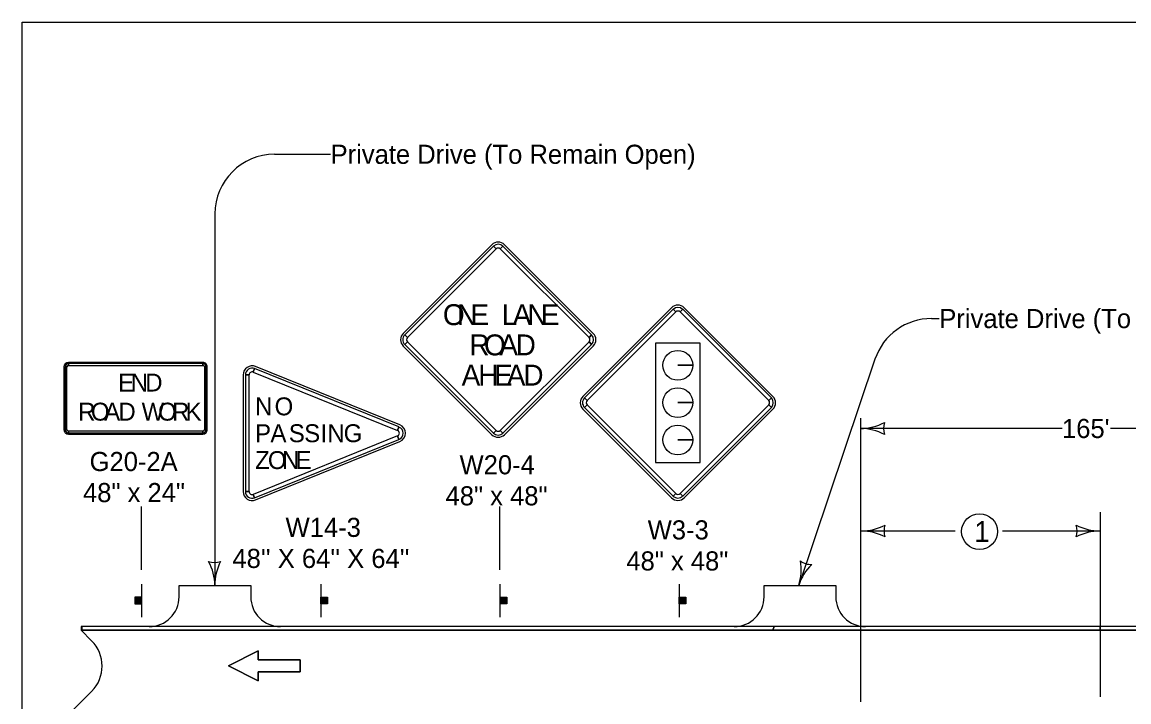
# Model space of a CAD drawing. Extents: x -2134934 to -2127057, y -2139046 to -2137036.
# Drawn here: x -2130232 to -2129305, y -2137605 to -2137036 of the extents above; entities that cross this region are included whole.
import ezdxf

# ---------------------------------------------------------------- set-up
doc = ezdxf.new("R2010")
doc.units = 0
for name, color, linetype in [('Barrier', 7, 'Continuous'), ('BridgeSuperStructureExisting', 7, 'Continuous'), ('Default', 7, 'Continuous'), ('DsnShtPlotIdentification', 7, 'Continuous'), ('DsnShtPlotShape', 7, 'Continuous')]:
    doc.layers.add(name, color=color, linetype=linetype)

msp = doc.modelspace()

# ---------------------------------------------------------------- linework, layer by layer
at = {"layer": 'Barrier'}
for p, q in [((-2129838.72, -2137222.31), (-2129912.96, -2137296.56)), ((-2129837.39, -2137223.64), (-2129835.18, -2137225.85)), ((-2129831.65, -2137225.85), (-2129829.44, -2137223.64)), ((-2129753.86, -2137296.56), (-2129828.11, -2137222.31)), ((-2129688.28, -2137275.12), (-2129762.53, -2137349.37)), ((-2129686.96, -2137276.45), (-2129684.75, -2137278.66)), ((-2129681.21, -2137278.66), (-2129679, -2137276.45)), ((-2129603.43, -2137349.37), (-2129677.68, -2137275.12)), ((-2129909.43, -2137300.09), (-2129911.64, -2137297.88)), ((-2129755.19, -2137297.88), (-2129757.4, -2137300.09)), ((-2129912.96, -2137307.16), (-2129838.72, -2137381.41)), ((-2129911.64, -2137305.84), (-2129909.43, -2137303.63)), ((-2129828.11, -2137381.41), (-2129753.86, -2137307.16)), ((-2129757.4, -2137303.63), (-2129755.19, -2137305.84)), ((-2130196.92, -2137324.64), (-2130196.92, -2137377.14)), ((-2130195.99, -2137324.64), (-2130194.42, -2137324.64)), ((-2130080.67, -2137320.89), (-2130193.17, -2137320.89)), ((-2130193.17, -2137323.39), (-2130193.17, -2137321.82)), ((-2130080.67, -2137321.82), (-2130080.67, -2137323.39)), ((-2130079.42, -2137324.64), (-2130077.86, -2137324.64)), ((-2130076.92, -2137377.14), (-2130076.92, -2137324.64)), ((-2130038.48, -2137329.01), (-2130037.31, -2137326.11)), ((-2129915.78, -2137373.25), (-2130036.61, -2137324.37)), ((-2129670.57, -2137323.34), (-2129683.07, -2137323.34)), ((-2129683.07, -2137323.34), (-2129670.57, -2137323.34)), ((-2130046.92, -2137331.32), (-2130046.92, -2137429.07)), ((-2130045.04, -2137331.32), (-2130041.92, -2137331.32)), ((-2129758.99, -2137352.9), (-2129761.2, -2137350.69)), ((-2129761.2, -2137358.65), (-2129758.99, -2137356.44)), ((-2129670.57, -2137354.59), (-2129683.07, -2137354.59)), ((-2129683.07, -2137354.59), (-2129670.57, -2137354.59)), ((-2129604.76, -2137350.69), (-2129606.96, -2137352.9)), ((-2129606.96, -2137356.44), (-2129604.76, -2137358.65)), ((-2129762.53, -2137359.98), (-2129688.28, -2137434.22)), ((-2129677.68, -2137434.22), (-2129603.43, -2137359.98)), ((-2129916.48, -2137374.98), (-2129917.66, -2137377.88)), ((-2130194.42, -2137377.14), (-2130195.99, -2137377.14)), ((-2130193.17, -2137379.95), (-2130193.17, -2137378.39)), ((-2130193.17, -2137380.89), (-2130080.67, -2137380.89)), ((-2130080.67, -2137378.39), (-2130080.67, -2137379.95)), ((-2130077.86, -2137377.14), (-2130079.42, -2137377.14)), ((-2129917.66, -2137382.52), (-2129916.48, -2137385.41)), ((-2129835.18, -2137377.87), (-2129837.39, -2137380.08)), ((-2129829.44, -2137380.08), (-2129831.65, -2137377.87)), ((-2130036.61, -2137436.03), (-2129915.78, -2137387.15)), ((-2129670.57, -2137385.84), (-2129683.07, -2137385.84)), ((-2129683.07, -2137385.84), (-2129670.57, -2137385.84)), ((-2130041.92, -2137429.07), (-2130045.04, -2137429.07)), ((-2129684.75, -2137430.69), (-2129686.96, -2137432.9)), ((-2129679, -2137432.9), (-2129681.21, -2137430.69)), ((-2130037.31, -2137434.29), (-2130038.48, -2137431.39))]:
    msp.add_line(p, q, dxfattribs=at)
for points in [[(-2129837.39, -2137223.64), (-2129911.64, -2137297.88), (-2129909.43, -2137300.09), (-2129835.18, -2137225.85), (-2129837.39, -2137223.64)], [(-2129755.19, -2137297.88), (-2129829.44, -2137223.64), (-2129831.65, -2137225.85), (-2129757.4, -2137300.09), (-2129755.19, -2137297.88)], [(-2129686.96, -2137276.45), (-2129761.2, -2137350.69), (-2129758.99, -2137352.9), (-2129684.75, -2137278.66), (-2129686.96, -2137276.45)], [(-2129604.76, -2137350.69), (-2129679, -2137276.45), (-2129681.21, -2137278.66), (-2129606.96, -2137352.9), (-2129604.76, -2137350.69)], [(-2129911.64, -2137305.84), (-2129837.39, -2137380.08), (-2129835.18, -2137377.87), (-2129909.43, -2137303.63), (-2129911.64, -2137305.84)], [(-2129829.44, -2137380.08), (-2129755.19, -2137305.84), (-2129757.4, -2137303.63), (-2129831.65, -2137377.87), (-2129829.44, -2137380.08)], [(-2129664.25, -2137304.73), (-2129701.71, -2137304.73), (-2129701.71, -2137404.62), (-2129664.25, -2137404.62), (-2129664.25, -2137304.73)], [(-2130195.99, -2137324.64), (-2130195.99, -2137377.14), (-2130194.42, -2137377.14), (-2130194.42, -2137324.64), (-2130195.99, -2137324.64)], [(-2130080.67, -2137321.82), (-2130193.17, -2137321.82), (-2130193.17, -2137323.39), (-2130080.67, -2137323.39), (-2130080.67, -2137321.82)], [(-2130077.86, -2137377.14), (-2130077.86, -2137324.64), (-2130079.42, -2137324.64), (-2130079.42, -2137377.14), (-2130077.86, -2137377.14)], [(-2129916.48, -2137374.98), (-2130037.31, -2137326.11), (-2130038.48, -2137329.01), (-2129917.66, -2137377.88), (-2129916.48, -2137374.98)], [(-2130045.04, -2137331.32), (-2130045.04, -2137429.07), (-2130041.92, -2137429.07), (-2130041.92, -2137331.32), (-2130045.04, -2137331.32)], [(-2129761.2, -2137358.65), (-2129686.96, -2137432.9), (-2129684.75, -2137430.69), (-2129758.99, -2137356.44), (-2129761.2, -2137358.65)], [(-2129679, -2137432.9), (-2129604.76, -2137358.65), (-2129606.96, -2137356.44), (-2129681.21, -2137430.69), (-2129679, -2137432.9)], [(-2130193.17, -2137379.95), (-2130080.67, -2137379.95), (-2130080.67, -2137378.39), (-2130193.17, -2137378.39), (-2130193.17, -2137379.95)], [(-2130037.31, -2137434.29), (-2129916.48, -2137385.41), (-2129917.66, -2137382.52), (-2130038.48, -2137431.39), (-2130037.31, -2137434.29)]]:
    msp.add_lwpolyline(points, close=True, dxfattribs=at)
for centre in [(-2129683.07, -2137323.34), (-2129683.07, -2137354.59), (-2129683.07, -2137385.84)]:
    msp.add_circle(centre, 12.5, dxfattribs=at)
for centre, radius, start, end in [((-2129833.41, -2137227.61), 7.5, 44.99999, 134.99974), ((-2129833.41, -2137227.61), 5.62, 44.99999, 134.99974), ((-2129833.41, -2137227.61), 2.5, 44.99999, 134.99974), ((-2129682.98, -2137280.43), 7.5, 44.99999, 134.99974), ((-2129682.98, -2137280.43), 5.62, 44.99999, 134.99974), ((-2129682.98, -2137280.43), 2.5, 44.99999, 134.99974), ((-2129907.66, -2137301.86), 7.5, 134.99974, 224.99995), ((-2129907.66, -2137301.86), 5.62, 134.99974, 224.99995), ((-2129907.66, -2137301.86), 2.5, 134.99974, 224.99995), ((-2129759.17, -2137301.86), 2.5, 315.00016, 44.9998), ((-2129759.17, -2137301.86), 5.62, 315.00016, 44.9998), ((-2129759.17, -2137301.86), 7.5, 315.00016, 44.9998), ((-2130193.17, -2137324.64), 3.75, 90.00021, 179.99985), ((-2130193.17, -2137324.64), 2.81, 90.00021, 179.99985), ((-2130193.17, -2137324.64), 1.25, 90.00021, 179.99985), ((-2130080.67, -2137324.64), 3.75, 0, 90.00021), ((-2130080.67, -2137324.64), 2.81, 0, 90.00021), ((-2130080.67, -2137324.64), 1.25, 0, 90.00021), ((-2130039.42, -2137331.32), 7.5, 67.97571, 179.99985), ((-2130039.42, -2137331.32), 5.62, 67.97571, 179.99985), ((-2130039.42, -2137331.32), 2.5, 67.97571, 179.99985), ((-2129757.23, -2137354.67), 7.5, 134.99974, 224.99995), ((-2129757.23, -2137354.67), 5.62, 134.99974, 224.99995), ((-2129757.23, -2137354.67), 2.5, 134.99974, 224.99995), ((-2129608.73, -2137354.67), 2.5, 315.00016, 44.9998), ((-2129608.73, -2137354.67), 5.62, 315.00016, 44.9998), ((-2129608.73, -2137354.67), 7.5, 315.00016, 44.9998), ((-2129918.59, -2137380.2), 5.62, 292.02456, 67.97541), ((-2129918.59, -2137380.2), 7.5, 292.02456, 67.97598), ((-2130193.17, -2137377.14), 3.75, 179.99985, 270.00006), ((-2130193.17, -2137377.14), 2.81, 179.99985, 270.00006), ((-2130193.17, -2137377.14), 1.25, 179.99985, 270.00006), ((-2130080.67, -2137377.14), 3.75, 270.00006, 0.00027), ((-2130080.67, -2137377.14), 2.81, 270.00006, 0.00027), ((-2130080.67, -2137377.14), 1.25, 270.00006, 0.00027), ((-2129918.59, -2137380.2), 2.5, 292.02456, 67.97541), ((-2129833.41, -2137376.11), 7.5, 224.99995, 315.00016), ((-2129833.41, -2137376.11), 5.62, 224.99995, 315.00016), ((-2129833.41, -2137376.11), 2.5, 224.99995, 315.00016), ((-2130039.42, -2137429.07), 7.5, 179.99985, 292.02456), ((-2130039.42, -2137429.07), 5.62, 179.99985, 292.02456), ((-2130039.42, -2137429.07), 2.5, 179.99985, 292.02456), ((-2129682.98, -2137428.92), 2.5, 224.99995, 315.00016), ((-2129682.98, -2137428.92), 7.5, 224.99995, 315.00016), ((-2129682.98, -2137428.92), 5.62, 224.99995, 315.00016)]:
    msp.add_arc(centre, radius, start, end, dxfattribs=at)
at = {"layer": 'BridgeSuperStructureExisting'}
for p, q in [((-2130020.59, -2137146.61), (-2129973.72, -2137146.61)), ((-2130070.59, -2137196.61), (-2130070.59, -2137507.67)), ((-2129470.64, -2137284.15), (-2129464.16, -2137284.15)), ((-2129518.02, -2137318.18), (-2129581.87, -2137507.67)), ((-2129530.12, -2137367.55), (-2129530.12, -2137605.16)), ((-2129361.44, -2137376.23), (-2129530.12, -2137376.23)), ((-2129152.26, -2137376.23), (-2129320.94, -2137376.23)), ((-2130131.95, -2137494.5), (-2130131.95, -2137441.62)), ((-2129831.95, -2137494.5), (-2129831.95, -2137441.62)), ((-2129329.62, -2137446.18), (-2129329.62, -2137601.07)), ((-2129450.84, -2137462.08), (-2129529.62, -2137462.08)), ((-2129329.62, -2137462.08), (-2129411.39, -2137462.08)), ((-2130131.95, -2137506.66), (-2130131.95, -2137534.16)), ((-2129981.95, -2137506.66), (-2129981.95, -2137534.16)), ((-2129831.95, -2137506.66), (-2129831.95, -2137534.16)), ((-2129681.95, -2137506.66), (-2129681.95, -2137534.16)), ((-2130137.28, -2137517.52), (-2130137.28, -2137523.11)), ((-2130136.96, -2137523.11), (-2130136.96, -2137517.52)), ((-2130136.73, -2137517.52), (-2130136.73, -2137523.11)), ((-2130136.41, -2137523.11), (-2130136.41, -2137517.52)), ((-2130136.19, -2137517.52), (-2130136.21, -2137523.11)), ((-2130135.78, -2137523.11), (-2130135.76, -2137517.52)), ((-2130135.55, -2137517.52), (-2130135.55, -2137523.11)), ((-2130135.12, -2137523.11), (-2130135.12, -2137517.52)), ((-2130134.75, -2137517.52), (-2130134.75, -2137523.11)), ((-2130134.43, -2137523.11), (-2130134.41, -2137517.52)), ((-2130134.2, -2137517.52), (-2130134.2, -2137523.11)), ((-2130133.94, -2137523.11), (-2130133.94, -2137517.52)), ((-2130133.6, -2137517.52), (-2130133.6, -2137523.11)), ((-2130133.4, -2137523.11), (-2130133.4, -2137517.52)), ((-2130133.17, -2137517.52), (-2130133.17, -2137523.11)), ((-2130132.91, -2137523.11), (-2130132.91, -2137517.52)), ((-2130132.65, -2137517.52), (-2130132.65, -2137523.11)), ((-2130132.36, -2137523.11), (-2130132.36, -2137517.52)), ((-2129981.54, -2137523.11), (-2129981.54, -2137517.52)), ((-2129981.26, -2137517.52), (-2129981.26, -2137523.11)), ((-2129980.99, -2137523.11), (-2129980.99, -2137517.52)), ((-2129980.73, -2137517.52), (-2129980.73, -2137523.11)), ((-2129980.51, -2137523.11), (-2129980.51, -2137517.52)), ((-2129980.3, -2137517.52), (-2129980.3, -2137523.11)), ((-2129979.96, -2137523.11), (-2129979.96, -2137517.52)), ((-2129979.7, -2137517.52), (-2129979.7, -2137523.11)), ((-2129979.47, -2137523.11), (-2129979.49, -2137517.52)), ((-2129979.16, -2137517.52), (-2129979.16, -2137523.11)), ((-2129978.78, -2137523.11), (-2129978.78, -2137517.52)), ((-2129978.35, -2137517.52), (-2129978.35, -2137523.11)), ((-2129978.12, -2137523.11), (-2129978.14, -2137517.52)), ((-2129977.71, -2137517.52), (-2129977.69, -2137523.11)), ((-2129977.49, -2137523.11), (-2129977.49, -2137517.52)), ((-2129977.17, -2137517.52), (-2129977.17, -2137523.11)), ((-2129976.94, -2137523.11), (-2129976.94, -2137517.52)), ((-2129976.62, -2137517.52), (-2129976.62, -2137523.11)), ((-2129831.54, -2137523.11), (-2129831.54, -2137517.52)), ((-2129831.26, -2137517.52), (-2129831.26, -2137523.11)), ((-2129830.99, -2137523.11), (-2129830.99, -2137517.52)), ((-2129830.73, -2137517.52), (-2129830.73, -2137523.11)), ((-2129830.51, -2137523.11), (-2129830.51, -2137517.52)), ((-2129830.3, -2137517.52), (-2129830.3, -2137523.11)), ((-2129829.96, -2137523.11), (-2129829.96, -2137517.52)), ((-2129829.7, -2137517.52), (-2129829.7, -2137523.11)), ((-2129829.47, -2137523.11), (-2129829.49, -2137517.52)), ((-2129829.16, -2137517.52), (-2129829.16, -2137523.11)), ((-2129828.78, -2137523.11), (-2129828.78, -2137517.52)), ((-2129828.35, -2137517.52), (-2129828.35, -2137523.11)), ((-2129828.12, -2137523.11), (-2129828.14, -2137517.52)), ((-2129827.71, -2137517.52), (-2129827.69, -2137523.11)), ((-2129827.49, -2137523.11), (-2129827.49, -2137517.52)), ((-2129827.17, -2137517.52), (-2129827.17, -2137523.11)), ((-2129826.94, -2137523.11), (-2129826.94, -2137517.52)), ((-2129826.62, -2137517.52), (-2129826.62, -2137523.11)), ((-2129681.54, -2137523.11), (-2129681.54, -2137517.52)), ((-2129681.26, -2137517.52), (-2129681.26, -2137523.11)), ((-2129680.99, -2137523.11), (-2129680.99, -2137517.52)), ((-2129680.73, -2137517.52), (-2129680.73, -2137523.11)), ((-2129680.51, -2137523.11), (-2129680.51, -2137517.52)), ((-2129680.3, -2137517.52), (-2129680.3, -2137523.11)), ((-2129679.96, -2137523.11), (-2129679.96, -2137517.52)), ((-2129679.7, -2137517.52), (-2129679.7, -2137523.11)), ((-2129679.48, -2137523.11), (-2129679.49, -2137517.52)), ((-2129679.16, -2137517.52), (-2129679.16, -2137523.11)), ((-2129678.78, -2137523.11), (-2129678.78, -2137517.52)), ((-2129678.35, -2137517.52), (-2129678.35, -2137523.11)), ((-2129678.13, -2137523.11), (-2129678.14, -2137517.52)), ((-2129677.71, -2137517.52), (-2129677.69, -2137523.11)), ((-2129677.49, -2137523.11), (-2129677.49, -2137517.52)), ((-2129677.17, -2137517.52), (-2129677.17, -2137523.11)), ((-2129676.94, -2137523.11), (-2129676.94, -2137517.52)), ((-2129676.63, -2137517.52), (-2129676.63, -2137523.11)), ((-2130182.57, -2137545.16), (-2130173.79, -2137553.95)), ((-2128680.12, -2137545.16), (-2130182.57, -2137545.16)), ((-2130182.57, -2137545.16), (-2130173.78, -2137553.95)), ((-2130015.59, -2137542.16), (-2130125.59, -2137542.16)), ((-2129525.87, -2137542.16), (-2129635.87, -2137542.16)), ((-2130173.78, -2137596.37), (-2130191.36, -2137613.95)), ((-2130173.79, -2137596.38), (-2130191.36, -2137613.95))]:
    msp.add_line(p, q, dxfattribs=at)
for points in [[(-2130100.59, -2137517.16), (-2130100.59, -2137507.67), (-2130040.59, -2137507.67), (-2130040.59, -2137517.16)], [(-2129610.87, -2137517.16), (-2129610.87, -2137507.67), (-2129550.87, -2137507.67), (-2129550.87, -2137517.16)], [(-2130034.3, -2137579.99), (-2130034.3, -2137587.49), (-2130059.3, -2137574.99), (-2130034.3, -2137562.49), (-2130034.3, -2137569.99), (-2129999.3, -2137569.99), (-2129999.3, -2137579.99), (-2130034.3, -2137579.99)]]:
    msp.add_lwpolyline(points, dxfattribs=at)
for points in [[(-2130132.05, -2137523.11), (-2130132.05, -2137517.48), (-2130137.67, -2137517.48), (-2130137.67, -2137523.11)], [(-2129981.86, -2137523.11), (-2129981.86, -2137517.48), (-2129976.23, -2137517.48), (-2129976.23, -2137523.11)], [(-2129831.86, -2137523.11), (-2129831.86, -2137517.48), (-2129826.23, -2137517.48), (-2129826.23, -2137523.11)], [(-2129681.86, -2137523.11), (-2129681.86, -2137517.48), (-2129676.23, -2137517.48), (-2129676.23, -2137523.11)], [(-2129999.3, -2137579.99), (-2129999.3, -2137569.99), (-2130034.3, -2137569.99), (-2130034.3, -2137562.49), (-2130059.3, -2137574.99), (-2130034.3, -2137587.49), (-2130034.3, -2137579.99)]]:
    msp.add_lwpolyline(points, close=True, dxfattribs=at)
msp.add_circle((-2129430.48, -2137462.58), 15, dxfattribs=at)
for centre, radius, start, end in [((-2130020.59, -2137196.61), 50, 90, 180), ((-2129470.64, -2137334.15), 50, 90, 161.37877), ((-2129529.62, -2137419.58), 42.5, 270, 298.07249), ((-2129493.99, -2137462.08), 16.42, 162.26665, 197.73335), ((-2129365.26, -2137462.08), 16.42, 342.26665, 17.73335), ((-2129329.62, -2137419.58), 42.5, 241.92751, 270), ((-2129529.62, -2137504.58), 42.5, 61.92751, 90), ((-2129329.62, -2137504.58), 42.5, 90, 118.07249), ((-2130125.59, -2137517.16), 25, 270, 360), ((-2130015.59, -2137517.16), 25, 180, 270), ((-2129635.87, -2137517.16), 25, 270, 360), ((-2129525.87, -2137517.16), 25, 180, 270), ((-2130195, -2137575.16), 30, 315, 45), ((-2130195, -2137575.16), 30, 315, 45)]:
    msp.add_arc(centre, radius, start, end, dxfattribs=at)
at = {"layer": 'Default'}
msp.add_lwpolyline([(-2130231.95, -2137035.95), (-2127096.96, -2137035.95), (-2127096.96, -2139045.94), (-2130231.95, -2139045.94)], close=True, dxfattribs=at)
at = {"layer": 'DsnShtPlotIdentification'}
for p, q in [((-2128680.12, -2137542.16), (-2130182.57, -2137542.16)), ((-2130182.57, -2137542.16), (-2130182.57, -2137545.16)), ((-2129602.5, -2137542.16), (-2130182.57, -2137542.16)), ((-2128680.12, -2137545.16), (-2130182.57, -2137545.16)), ((-2130182.57, -2137545.16), (-2129603.51, -2137545.16)), ((-2130181.95, -2137542.16), (-2130181.95, -2137545.16)), ((-2129602.5, -2137542.16), (-2129603.51, -2137545.16)), ((-2129603.51, -2137545.16), (-2129602.5, -2137542.16)), ((-2129603.51, -2137545.16), (-2129329.62, -2137545.16)), ((-2129329.62, -2137542.16), (-2129602.5, -2137542.16)), ((-2129329.62, -2137542.16), (-2129329.62, -2137545.16)), ((-2129296.37, -2137542.16), (-2129329.62, -2137542.16)), ((-2129329.62, -2137545.16), (-2129329.62, -2137542.16)), ((-2129329.62, -2137545.16), (-2129296.24, -2137545.16))]:
    msp.add_line(p, q, dxfattribs=at)
msp.add_lwpolyline([(-2130182.37, -2137545.16), (-2128872.37, -2137545.16)], dxfattribs=at)
at = {"layer": 'DsnShtPlotShape'}
for centre, radius, start, end in [((-2129530.12, -2137333.73), 42.5, 270, 298.07249), ((-2129494.48, -2137376.23), 16.42, 162.26665, 197.73335), ((-2129530.12, -2137418.73), 42.5, 61.92751, 90), ((-2130071.03, -2137472.04), 16.42, 252.97281, 288.43951), ((-2130113.08, -2137508.19), 42.5, 0.70616, 28.77865), ((-2130028.09, -2137507.15), 42.5, 152.63367, 180.70616), ((-2129622.31, -2137494.6), 42.5, 342.08492, 10.15741), ((-2129541.43, -2137520.74), 42.5, 134.01243, 162.08492), ((-2129570.91, -2137473.76), 16.42, 234.35157, 269.81827)]:
    msp.add_arc(centre, radius, start, end, dxfattribs=at)

# ---------------------------------------------------------------- texts
at = {"layer": 'Barrier'}
for s, height, p in [('O', 17.5, (-2129879.7, -2137289.67)), ('N', 17.5, (-2129867.92, -2137289.67)), ('E', 17.5, (-2129856.7, -2137289.67)), ('L', 17.5, (-2129830.45, -2137289.67)), ('A', 17.5, (-2129821.25, -2137289.67)), ('N', 17.5, (-2129808.98, -2137289.67)), ('E', 17.5, (-2129797.75, -2137289.67)), ('R', 17.5, (-2129857.59, -2137314.98)), ('O', 17.5, (-2129845.3, -2137314.98)), ('A', 17.5, (-2129832.46, -2137314.98)), ('D', 17.5, (-2129818.81, -2137314.98)), ('A', 17.5, (-2129864.03, -2137340.3)), ('H', 17.5, (-2129850.16, -2137340.3)), ('E', 17.5, (-2129836.95, -2137340.3)), ('A', 17.5, (-2129826.23, -2137340.3)), ('D', 17.5, (-2129812.37, -2137340.3)), ('E', 15, (-2130151.6, -2137345.26)), ('N', 15, (-2130140.98, -2137345.26)), ('D', 15, (-2130128.89, -2137345.26)), ('R', 15, (-2130185.06, -2137369.64)), ('O', 15, (-2130174.38, -2137369.64)), ('A', 15, (-2130163.22, -2137369.64)), ('D', 15, (-2130151.36, -2137369.64)), ('W', 15, (-2130131.91, -2137369.64)), ('O', 15, (-2130118.18, -2137369.64)), ('R', 15, (-2130106.41, -2137369.64)), ('K', 15, (-2130095.11, -2137369.64)), ('N', 15, (-2130036.95, -2137365.2)), ('O', 15, (-2130020.61, -2137365.2)), ('P', 15, (-2130036.95, -2137387.7)), ('A', 15, (-2130024.06, -2137387.7)), ('S', 15, (-2130008.71, -2137387.7)), ('S', 15, (-2129995.82, -2137387.7)), ('I', 15, (-2129982.22, -2137387.7)), ('N', 15, (-2129976.36, -2137387.7)), ('G', 15, (-2129962.77, -2137387.7)), ('G20-2A', 16, (-2130175.45, -2137411.89)), ('Z', 15, (-2130036.95, -2137410.2)), ('O', 15, (-2130026.21, -2137410.2)), ('N', 15, (-2130014.38, -2137410.2)), ('E', 15, (-2130003.02, -2137410.2)), ('W20-4', 16, (-2129865.78, -2137414.61)), ('48" x 24"', 16, (-2130180.99, -2137437.89)), ('48" x 48"', 16, (-2129877.48, -2137440.61)), ('W14-3', 16, (-2130011.41, -2137467.03)), ('W3-3', 16, (-2129708.27, -2137469.14)), ("48'' X 64'' X 64''", 16, (-2130055.9, -2137493.03)), ('48" x 48"', 16, (-2129726.15, -2137495.14))]:
    msp.add_text(s, height=height, dxfattribs=at).set_placement(p)
at = {"layer": 'BridgeSuperStructureExisting'}
for s, height, p in [('Private Drive (To Remain Open)', 16, (-2129973.72, -2137154.61)), ('Private Drive (To Remain Open)', 16, (-2129464.16, -2137292.15)), ("165'", 16, (-2129361.44, -2137384.23)), ('1', 17.5, (-2129434.94, -2137471.33))]:
    msp.add_text(s, height=height, dxfattribs=at).set_placement(p)

doc.saveas('drawing.dxf')
